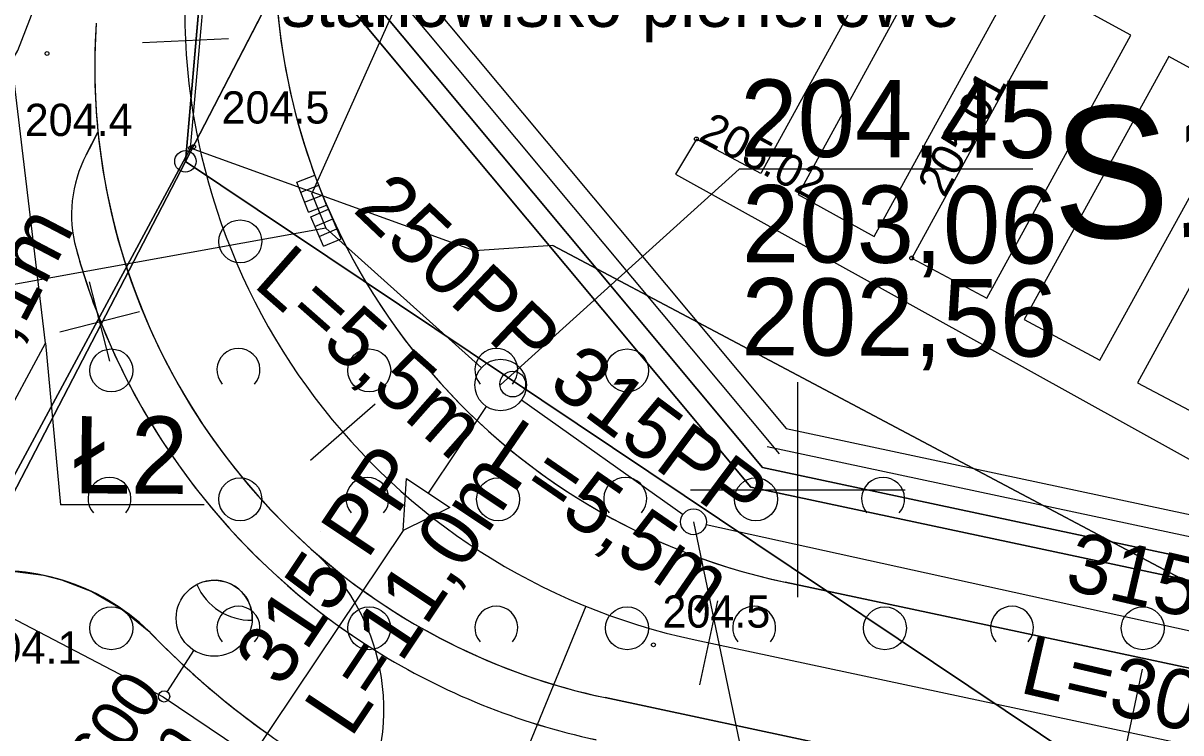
# Model space of a CAD drawing. Extents: x 6512606 to 6513006, y 6022524 to 6022728.
# Drawn here: x 6512731.97 to 6512758.91, y 6022594.34 to 6022610.86 of the extents above; entities that cross this region are included whole.
import ezdxf

# ---------------------------------------------------------------- set-up
doc = ezdxf.new("R2010")
doc.units = 0
for name, color, linetype in [('20', 7, 'Continuous'), ('202-punkt graniczny', 7, 'Continuous'), ('217-kontur klasyfikacyjny', 7, 'Continuous'), ('218-kontur użytku gruntowego', 7, 'Continuous'), ('219-działka ewidencyjna', 7, 'Continuous'), ('4', 7, 'Continuous'), ('chodnik (powierzchnia)', 7, 'Continuous'), ('Default', 7, 'Continuous'), ('E_OSW_KABLE', 7, 'Continuous'), ('E_OSW_LAMPA', 7, 'Continuous'), ('jezdnia', 7, 'Continuous'), ('kolor_kostka_bet', 7, 'Continuous'), ('kolor_sc_rowerowa', 7, 'Continuous'), ('Komentarz lub etykieta na mapie', 7, 'Continuous'), ('Level 47', 7, 'Continuous'), ('Level 55', 7, 'Continuous'), ('Level 60', 7, 'Continuous'), ('maxp_inst_wodociągowa', 7, 'Continuous'), ('maxp_kan_deszczowa', 7, 'Continuous'), ('maxp_kratki', 7, 'Continuous'), ('maxp_kraw_nawierzchni', 7, 'Continuous'), ('maxp_kraw_obniżony', 7, 'Continuous'), ('maxp_krawężnik', 7, 'Continuous'), ('maxp_likwidacje', 7, 'Continuous'), ('maxp_obrzeże', 7, 'Continuous'), ('maxp_opornik', 7, 'Continuous'), ('maxp_os', 7, 'Continuous'), ('maxp_ramka_2', 7, 'Continuous'), ('ogrodzenie', 7, 'Continuous'), ('ogrodzenie trwałe', 7, 'Continuous'), ('pikieta naturalna', 7, 'Continuous'), ('pikieta naturalna-Atr2', 7, 'Continuous'), ('punkt wysokościowy naturalny', 7, 'Continuous'), ('punkt wysokościowy naturalny-Atr2', 7, 'Continuous'), ('punkt wysokościowy sztuczny', 7, 'Continuous'), ('punkt wysokościowy sztuczny-Atr2', 7, 'Continuous'), ('zadrzewienie  zakrzewienie', 7, 'Continuous')]:
    doc.layers.add(name, color=color, linetype=linetype)

# ---------------------------------------------------------------- blocks, each defined once
blk = doc.blocks.new('202')
at = {"layer": 'Default'}
blk.add_circle((0, 0), 2.5, dxfattribs=at)
blk = doc.blocks.new('PW01')
at = {"layer": 'Default'}
blk.add_circle((0, 0), 0.45, dxfattribs=at)
blk = doc.blocks.new('PW02')
at = {"layer": 'Default'}
blk.add_circle((0, 0), 0.45, dxfattribs=at)
blk = doc.blocks.new('OTZK1')
at = {"layer": 'Default'}
blk.add_circle((0, 0), 5, dxfattribs=at)
blk = doc.blocks.new('OTZK2')
at = {"layer": 'Default'}
blk.add_arc((0, 0), 5, 318.85, 221.162, dxfattribs=at)

msp = doc.modelspace()

# ---------------------------------------------------------------- linework, layer by layer
for p, q in [((6512739.753, 6022611.813), (6512749.181, 6022600.515)), ((6512749.181, 6022600.515), (6512804.476, 6022588.74))]:
    msp.add_line(p, q)
at = {"layer": '20'}
for p, q in [((6512738.693, 6022606.882), (6512744.215, 6022619.226)), ((6512743.084, 6022602.437), (6512748.637, 6022607.462)), ((6512755.471, 6022607.462), (6512748.637, 6022607.462)), ((6512739.016, 6022606.082), (6512719.123, 6022602.5)), ((6512732.494, 6022603.407), (6512732.84, 6022599.645)), ((6512736.185, 6022599.645), (6512732.84, 6022599.645)), ((6512747.573, 6022599.253), (6512750.914, 6022583.162))]:
    msp.add_line(p, q, dxfattribs=at)
at = {"layer": '217-kontur klasyfikacyjny'}
for points in [[(6512749.37, 6022633.95), (6512735.75, 6022607.64)], [(6512735.75, 6022607.64), (6512728.87, 6022594.38)], [(6512735.75, 6022607.64), (6512773.05, 6022582.65)], [(6512773.05, 6022582.65), (6512735.75, 6022607.64)]]:
    msp.add_lwpolyline(points, dxfattribs=at)
at = {"layer": '218-kontur użytku gruntowego'}
for points in [[(6512735.75, 6022607.64), (6512749.37, 6022633.95)], [(6512749.37, 6022633.95), (6512735.75, 6022607.64)], [(6512737.73, 6022630.38), (6512735.75, 6022607.64)], [(6512735.75, 6022607.64), (6512737.73, 6022630.38)], [(6512735.75, 6022607.64), (6512728.87, 6022594.38)], [(6512728.87, 6022594.38), (6512735.75, 6022607.64)], [(6512735.75, 6022607.64), (6512773.05, 6022582.65)], [(6512773.05, 6022582.65), (6512735.75, 6022607.64)]]:
    msp.add_lwpolyline(points, dxfattribs=at)
at = {"layer": '219-działka ewidencyjna'}
for points in [[(6512739.15, 6022646.62), (6512735.75, 6022607.64)], [(6512751.92, 6022638.86), (6512735.75, 6022607.64)], [(6512735.75, 6022607.64), (6512728.87, 6022594.38)], [(6512773.05, 6022582.65), (6512735.75, 6022607.64)]]:
    msp.add_lwpolyline(points, dxfattribs=at)
at = {"layer": '4'}
for points in [[(6512739.15, 6022646.62), (6512735.75, 6022607.64)], [(6512751.92, 6022638.86), (6512735.75, 6022607.64)], [(6512735.75, 6022607.64), (6512728.87, 6022594.38)], [(6512773.05, 6022582.65), (6512735.75, 6022607.64)]]:
    msp.add_lwpolyline(points, dxfattribs=at)
at = {"layer": 'chodnik (powierzchnia)'}
msp.add_lwpolyline([(6512752.5, 6022613.48), (6512749.14, 6022607.36), (6512747.64, 6022608.16), (6512747.15, 6022607.34), (6512770.57, 6022594.35), (6512774.41, 6022601.39), (6512774.96, 6022601.08), (6512775.93, 6022602.8), (6512775.35, 6022603.13), (6512779.14, 6022609.99), (6512778.27, 6022610.47), (6512774.5, 6022603.63), (6512772.74, 6022604.6), (6512776.52, 6022611.46)], dxfattribs=at)
for points in [[(6512753.36, 6022613), (6512750.01, 6022606.87), (6512751.78, 6022605.89), (6512755.14, 6022612.03)], [(6512756.01, 6022611.53), (6512752.65, 6022605.39), (6512754.4, 6022604.46), (6512757.75, 6022610.58)], [(6512758.63, 6022610.08), (6512755.27, 6022603.96), (6512757.03, 6022603.01), (6512760.39, 6022609.12)], [(6512761.26, 6022608.62), (6512757.9, 6022602.49), (6512759.65, 6022601.56), (6512763, 6022607.67)]]:
    msp.add_lwpolyline(points, close=True, dxfattribs=at)
at = {"layer": 'Default'}
for p, q in [((6512750, 6022597.5), (6512750, 6022602.5)), ((6512747.5, 6022600), (6512752.5, 6022600))]:
    msp.add_line(p, q, dxfattribs=at)
at = {"layer": 'E_OSW_KABLE'}
msp.add_line((6512735.232, 6022595.177), (6512744.976, 6022588.649), dxfattribs=at)
msp.add_lwpolyline([(6512724.836, 6022600.607), (6512735.232, 6022595.177), (6512735.232, 6022595.177)], dxfattribs=at)
at = {"layer": 'E_OSW_LAMPA'}
msp.add_line((6512735.938, 6022596.257), (6512735.325, 6022595.3), dxfattribs=at)
for centre, radius in [((6512736.421, 6022597.008), 0.885), ((6512735.253, 6022595.189), 0.132)]:
    msp.add_circle(centre, radius, dxfattribs=at)
for centre, radius, start, end in [((6512736.421, 6022597.008), 0.885, 357.2094, 117.2094), ((6512737.27, 6022598.326), 1.362, 202.9801, 271.4387)]:
    msp.add_arc(centre, radius, start, end, dxfattribs=at)
at = {"layer": 'jezdnia'}
msp.add_lwpolyline([(6512731.08, 6022620.65), (6512728.82, 6022611.46), (6512722.83, 6022600.42), (6512717.94, 6022592.02), (6512712.43, 6022580.37), (6512709.04, 6022573), (6512712.21, 6022570.83), (6512715.01, 6022579.3), (6512720.33, 6022590.74), (6512725.35, 6022598.98), (6512731.85, 6022610.22), (6512735.75, 6022620.3)], close=True, dxfattribs=at)
at = {"layer": 'kolor_kostka_bet'}
for p, q in [((6512749.181, 6022600.515), (6512739.753, 6022611.813)), ((6512739.241, 6022611.647), (6512748.908, 6022600.062)), ((6512748.908, 6022600.062), (6512739.241, 6022611.647)), ((6512804.476, 6022588.74), (6512749.181, 6022600.515)), ((6512748.908, 6022600.062), (6512804.444, 6022588.236)), ((6512804.444, 6022588.236), (6512748.908, 6022600.062)), ((6512810.802, 6022584.837), (6512749.708, 6022597.847)), ((6512749.708, 6022597.847), (6512810.802, 6022584.837)), ((6512745.515, 6022595.161), (6512751.029, 6022593.987)), ((6512751.029, 6022593.987), (6512745.515, 6022595.161))]:
    msp.add_line(p, q, dxfattribs=at)
for points in [[(6512733.715, 6022608.318), (6512733.626, 6022608.148), (6512733.569, 6022608.038), (6512733.44, 6022607.792)], [(6512733.714, 6022604.066), (6512733.773, 6022603.916)]]:
    msp.add_lwpolyline(points, dxfattribs=at)
for centre, radius, start, end in [((6512752.832, 6022612.518), 15, 176.0865, 257.9783), ((6512752.832, 6022612.518), 15, 178.633, 257.9783), ((6512748.639, 6022609.832), 15, 176.0865, 257.9783), ((6512748.639, 6022609.832), 15, 185.7922, 228.4237), ((6512736.099, 6022606.403), 3, 152.4212, 195.2964), ((6512748.639, 6022609.832), 16, 195.2964, 201.1244), ((6512748.639, 6022609.832), 16, 201.7004, 238.0438), ((6512735.367, 6022594.871), 5, 16.0956, 48.4237), ((6512735.367, 6022594.871), 5, 16.0956, 48.4237), ((6512748.639, 6022609.832), 15, 228.4237, 257.9783), ((6512731.417, 6022593.117), 5, 44.1446, 152.4212), ((6512748.639, 6022609.832), 19, 224.1434, 242.861), ((6512748.639, 6022609.832), 16, 238.0438, 257.9777)]:
    msp.add_arc(centre, radius, start, end, dxfattribs=at)
at = {"layer": 'kolor_sc_rowerowa'}
for points in [[(6512733.44, 6022607.792), (6512733.569, 6022608.038), (6512733.626, 6022608.148), (6512733.715, 6022608.318)], [(6512733.773, 6022603.916), (6512733.754, 6022603.911), (6512733.714, 6022604.066)]]:
    msp.add_lwpolyline(points, dxfattribs=at)
for centre, radius, start, end in [((6512748.639, 6022609.832), 15, 176.0865, 185.7922), ((6512736.099, 6022606.403), 3, 152.4212, 195.2964), ((6512748.639, 6022609.832), 16, 195.2964, 201.1244), ((6512748.639, 6022609.832), 16, 201.7004, 238.0438), ((6512731.417, 6022593.117), 5, 44.1437, 152.4212), ((6512748.639, 6022609.832), 19, 224.1437, 242.861), ((6512735.367, 6022594.871), 5, 337.0866, 16.0956), ((6512735.367, 6022594.871), 5, 337.0866, 16.0956), ((6512748.639, 6022609.832), 16, 238.0438, 257.9777)]:
    msp.add_arc(centre, radius, start, end, dxfattribs=at)
at = {"layer": 'Level 55'}
msp.add_circle((6512743.366, 6022602.458), 0.3, dxfattribs=at)
at = {"layer": 'Level 60'}
for points in [[(6512736.752, 6022610.494), (6512734.754, 6022610.397)], [(6512740.167, 6022601.993), (6512738.657, 6022600.681)], [(6512748.128, 6022597.416), (6512747.711, 6022595.46)], [(6512758.013, 6022595.823), (6512757.388, 6022592.888)]]:
    msp.add_lwpolyline(points, dxfattribs=at)
at = {"layer": 'maxp_kan_deszczowa'}
for p, q in [((6512738.693, 6022606.882), (6512739.016, 6022606.082)), ((6512739.016, 6022606.082), (6512742.637, 6022602.837)), ((6512742.75, 6022601.938), (6512741.398, 6022599.92)), ((6512743.573, 6022602.09), (6512747.329, 6022599.426)), ((6512747.866, 6022599.189), (6512762.271, 6022596.024)), ((6512740.813, 6022599.048), (6512736.944, 6022593.273))]:
    msp.add_line(p, q, dxfattribs=at)
for points in [[(6512731.394, 6022601.378), (6512732.494, 6022603.407), (6512731.52, 6022611.602)], [(6512804.444, 6022588.236), (6512787.447, 6022591.855), (6512780, 6022593.441), (6512780.016, 6022593.468), (6512767.827, 6022596.033), (6512755.283, 6022598.704), (6512748.908, 6022600.062), (6512739.241, 6022611.647)], [(6512731.729, 6022598.107), (6512732.446, 6022598.01), (6512732.865, 6022597.903), (6512733.569, 6022597.63), (6512734.237, 6022597.246), (6512734.899, 6022596.705), (6512734.956, 6022596.648), (6512735.048, 6022596.555), (6512735.142, 6022596.459), (6512735.45, 6022596.156), (6512735.733, 6022595.888), (6512735.923, 6022595.715), (6512736.102, 6022595.556), (6512736.281, 6022595.4), (6512736.462, 6022595.247), (6512736.636, 6022595.103), (6512736.764, 6022595), (6512736.897, 6022594.895), (6512737.024, 6022594.796), (6512737.223, 6022594.644), (6512737.345, 6022594.553), (6512737.483, 6022594.452), (6512737.693, 6022594.302)]]:
    msp.add_lwpolyline(points, dxfattribs=at)
msp.add_lwpolyline([(6512741.901, 6022599.583), (6512740.813, 6022599.048), (6512740.894, 6022600.258)], close=True, dxfattribs=at)
for centre, radius in [((6512743.084, 6022602.437), 0.6), ((6512747.573, 6022599.253), 0.3)]:
    msp.add_circle(centre, radius, dxfattribs=at)
at = {"layer": 'maxp_kratki'}
for p, q in [((6512738.341, 6022607.153), (6512738.76, 6022607.318)), ((6512738.341, 6022607.153), (6512738.76, 6022607.318)), ((6512739.034, 6022606.62), (6512738.76, 6022607.318)), ((6512739.034, 6022606.62), (6512738.76, 6022607.318)), ((6512738.615, 6022606.456), (6512738.341, 6022607.153)), ((6512738.615, 6022606.456), (6512738.341, 6022607.153)), ((6512738.433, 6022606.92), (6512738.852, 6022607.085)), ((6512738.433, 6022606.92), (6512738.852, 6022607.085)), ((6512738.524, 6022606.688), (6512738.943, 6022606.852)), ((6512738.524, 6022606.688), (6512738.943, 6022606.852)), ((6512738.615, 6022606.456), (6512739.034, 6022606.62)), ((6512738.615, 6022606.456), (6512739.034, 6022606.62)), ((6512738.666, 6022606.35), (6512739.079, 6022606.529)), ((6512738.666, 6022606.35), (6512739.079, 6022606.529)), ((6512739.376, 6022605.841), (6512739.079, 6022606.529)), ((6512739.376, 6022605.841), (6512739.079, 6022606.529)), ((6512738.963, 6022605.663), (6512738.666, 6022606.35)), ((6512738.963, 6022605.663), (6512738.666, 6022606.35)), ((6512738.765, 6022606.121), (6512739.179, 6022606.3)), ((6512738.765, 6022606.121), (6512739.179, 6022606.3)), ((6512738.864, 6022605.892), (6512739.277, 6022606.07)), ((6512738.864, 6022605.892), (6512739.277, 6022606.07)), ((6512738.963, 6022605.663), (6512739.376, 6022605.841)), ((6512738.963, 6022605.663), (6512739.376, 6022605.841))]:
    msp.add_line(p, q, dxfattribs=at)
at = {"layer": 'maxp_kraw_nawierzchni'}
msp.add_arc((6512735.367, 6022594.871), 5, 337.0866, 16.0956, dxfattribs=at)
at = {"layer": 'maxp_kraw_obniżony'}
msp.add_line((6512745.515, 6022595.161), (6512751.029, 6022593.987), dxfattribs=at)
msp.add_arc((6512748.639, 6022609.832), 15, 228.4237, 257.9783, dxfattribs=at)
at = {"layer": 'maxp_krawężnik'}
msp.add_line((6512749.708, 6022597.847), (6512811.419, 6022584.705), dxfattribs=at)
for centre, radius, start, end in [((6512752.832, 6022612.518), 15, 176.0865, 257.9783), ((6512748.639, 6022609.832), 15, 176.0865, 228.4237), ((6512735.367, 6022594.871), 5, 16.0956, 48.4237)]:
    msp.add_arc(centre, radius, start, end, dxfattribs=at)
at = {"layer": 'maxp_likwidacje'}
for p, q in [((6512733.993, 6022602.987), (6512733.515, 6022604.836)), ((6512732.83, 6022603.673), (6512734.678, 6022604.15))]:
    msp.add_line(p, q, dxfattribs=at)
at = {"layer": 'maxp_obrzeże'}
msp.add_line((6512733.44, 6022607.792), (6512733.715, 6022608.318), dxfattribs=at)
for centre, radius, start, end in [((6512736.099, 6022606.403), 3, 152.4212, 195.2964), ((6512748.639, 6022609.832), 16, 195.2964, 238.0438), ((6512731.417, 6022593.117), 5, 44.1437, 152.4212), ((6512748.639, 6022609.832), 19, 224.1434, 242.861), ((6512748.639, 6022609.832), 16, 238.0438, 257.9783)]:
    msp.add_arc(centre, radius, start, end, dxfattribs=at)
at = {"layer": 'maxp_opornik'}
msp.add_line((6512733.569, 6022608.038), (6512733.715, 6022608.318), dxfattribs=at)
at = {"layer": 'maxp_os'}
for p, q in [((6512745.064, 6022597.288), (6512743.689, 6022593.92)), ((6512747.611, 6022596.504), (6512812.444, 6022582.698))]:
    msp.add_line(p, q, dxfattribs=at)
for centre, radius, start, end in [((6512750.735, 6022611.175), 15, 176.0865, 257.9783), ((6512742.147, 6022602.819), 5, 229.2316, 229.2331)]:
    msp.add_arc(centre, radius, start, end, dxfattribs=at)
at = {"layer": 'maxp_ramka_2'}
for p, q in [((6512740.778, 6022612.146), (6512749.728, 6022601.421)), ((6512740.266, 6022611.979), (6512749.565, 6022600.835)), ((6512749.728, 6022601.421), (6512772.409, 6022596.591)), ((6512749.285, 6022601.004), (6512804.509, 6022589.244))]:
    msp.add_line(p, q, dxfattribs=at)
at = {"layer": 'ogrodzenie'}
for p, q in [((6512739.241, 6022611.647), (6512748.908, 6022600.062)), ((6512748.908, 6022600.062), (6512804.444, 6022588.236))]:
    msp.add_line(p, q, dxfattribs=at)
at = {"layer": 'ogrodzenie trwałe'}
for points in [[(6512755.94, 6022562.73), (6512746.11, 6022568.85), (6512734.85, 6022575.76), (6512722.94, 6022583.56), (6512729.52, 6022596.18), (6512735.87, 6022607.95), (6512736.94, 6022619.99)], [(6512744.3, 6022605.68), (6512748.08, 6022603.68), (6512764.51, 6022594.96), (6512770, 6022592.05), (6512774.96, 6022601.08), (6512775.93, 6022602.8), (6512779.97, 6022610.83), (6512780.39, 6022611.67), (6512774.54, 6022615.22)]]:
    msp.add_lwpolyline(points, dxfattribs=at)
at = {"layer": 'zadrzewienie  zakrzewienie'}
msp.add_lwpolyline([(6512764.51, 6022594.96), (6512748.08, 6022603.68), (6512744.3, 6022605.68), (6512742.48, 6022605.56), (6512735.87, 6022607.95), (6512729.52, 6022596.18)], dxfattribs=at)

# ---------------------------------------------------------------- block references
at = {"layer": '202-punkt graniczny', "xscale": 0.1, "yscale": 0.10000000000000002}
msp.add_blockref('202', (6512735.75, 6022607.64), dxfattribs=at)
at = {"layer": 'pikieta naturalna', "xscale": 0.1, "yscale": 0.10000000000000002}
for p in [(6512732.53, 6022610.15), (6512735.87, 6022607.95)]:
    msp.add_blockref('PW01', p, dxfattribs=at)
at = {"layer": 'punkt wysokościowy naturalny', "xscale": 0.1, "yscale": 0.10000000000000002}
for p in [(6512735.94, 6022607.98), (6512746.64, 6022596.39)]:
    msp.add_blockref('PW01', p, dxfattribs=at)
at = {"layer": 'punkt wysokościowy sztuczny', "xscale": 0.1, "yscale": 0.10000000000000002}
for p in [(6512747.64, 6022608.16), (6512752.65, 6022605.39)]:
    msp.add_blockref('PW02', p, dxfattribs=at)
at = {"layer": 'zadrzewienie  zakrzewienie', "xscale": 0.1, "yscale": 0.10000000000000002}
for name, p in [('OTZK1', (6512737.026, 6022605.776)), ('OTZK1', (6512734.026, 6022602.776)), ('OTZK2', (6512736.984, 6022602.787)), ('OTZK1', (6512740.026, 6022602.776)), ('OTZK2', (6512742.984, 6022602.787)), ('OTZK1', (6512746.026, 6022602.776)), ('OTZK2', (6512733.984, 6022599.787)), ('OTZK1', (6512737.026, 6022599.776)), ('OTZK2', (6512739.984, 6022599.787)), ('OTZK1', (6512743.026, 6022599.776)), ('OTZK2', (6512745.984, 6022599.787)), ('OTZK1', (6512749.026, 6022599.776)), ('OTZK2', (6512751.984, 6022599.787)), ('OTZK1', (6512734.026, 6022596.776)), ('OTZK2', (6512736.984, 6022596.787)), ('OTZK1', (6512740.026, 6022596.776)), ('OTZK2', (6512742.984, 6022596.787)), ('OTZK1', (6512746.026, 6022596.776)), ('OTZK2', (6512748.984, 6022596.787)), ('OTZK1', (6512752.026, 6022596.776)), ('OTZK2', (6512754.984, 6022596.787)), ('OTZK1', (6512758.026, 6022596.776))]:
    msp.add_blockref(name, p, dxfattribs=at)

# ---------------------------------------------------------------- texts
at = {"layer": 'Komentarz lub etykieta na mapie'}
msp.add_text('stanowisko plenerowe', height=1.2, dxfattribs=at).set_placement((6512737.98, 6022610.77))
at = {"layer": 'Level 47'}
for s, height, rotation, p in [('204,45', 1.7971, 359.7281, (6512748.652, 6022607.75)), ('250PP', 1.3824, 316.4096, (6512739.621, 6022606.49)), ('203,06', 1.7971, 359.7281, (6512748.693, 6022605.295)), ('%%c75PP, L=73,1m', 1.3824, 62.3574, (6512726.582, 6022593.48)), ('L=5,5m', 1.3824, 318.5889, (6512737.297, 6022604.751)), ('202,56', 1.7971, 359.7281, (6512748.683, 6022603.13)), ('315PP', 1.3824, 323.3301, (6512744.151, 6022602.37)), ('Ł2', 1.7971, 359.7281, (6512733.136, 6022599.915)), ('L=5,5m', 1.3824, 325.5094, (6512742.695, 6022600.575)), ('315 PP', 1.3824, 56.2771, (6512737.981, 6022595.359)), ('L=11,0m', 1.3824, 56.2771, (6512739.599, 6022594.196)), ('315 PP', 1.3824, 346.919, (6512756.175, 6022597.699)), ('L=30,80m', 1.3824, 346.919, (6512755.124, 6022595.287)), ('ZB-DN1600', 1.1134, 56.3241, (6512730.909, 6022588.727)), ('L=7,7m', 1.1134, 56.3241, (6512733.341, 6022589.957))]:
    msp.add_text(s, height=height, rotation=rotation, dxfattribs=at).set_placement(p)
at = {"layer": 'maxp_inst_wodociągowa'}
msp.add_text('S1', height=3.0671, rotation=0.5777, dxfattribs=at).set_placement((6512755.936, 6022605.845))
at = {"layer": 'pikieta naturalna-Atr2'}
for s, p in [('204.4', (6512732.01, 6022608.23)), ('204.1', (6512730.82, 6022595.95))]:
    msp.add_text(s, height=0.75, dxfattribs=at).set_placement(p)
at = {"layer": 'punkt wysokościowy naturalny-Atr2'}
for p in [(6512736.59, 6022608.52), (6512746.85, 6022596.79)]:
    msp.add_text('204.5', height=0.75, dxfattribs=at).set_placement(p)
at = {"layer": 'punkt wysokościowy sztuczny-Atr2'}
for s, rotation, p in [('205.01', 61.311, (6512753.41, 6022606.77)), ('205.02', 331.927, (6512747.66, 6022608.15))]:
    msp.add_text(s, height=0.75, rotation=rotation, dxfattribs=at).set_placement(p)

doc.saveas('drawing.dxf')
